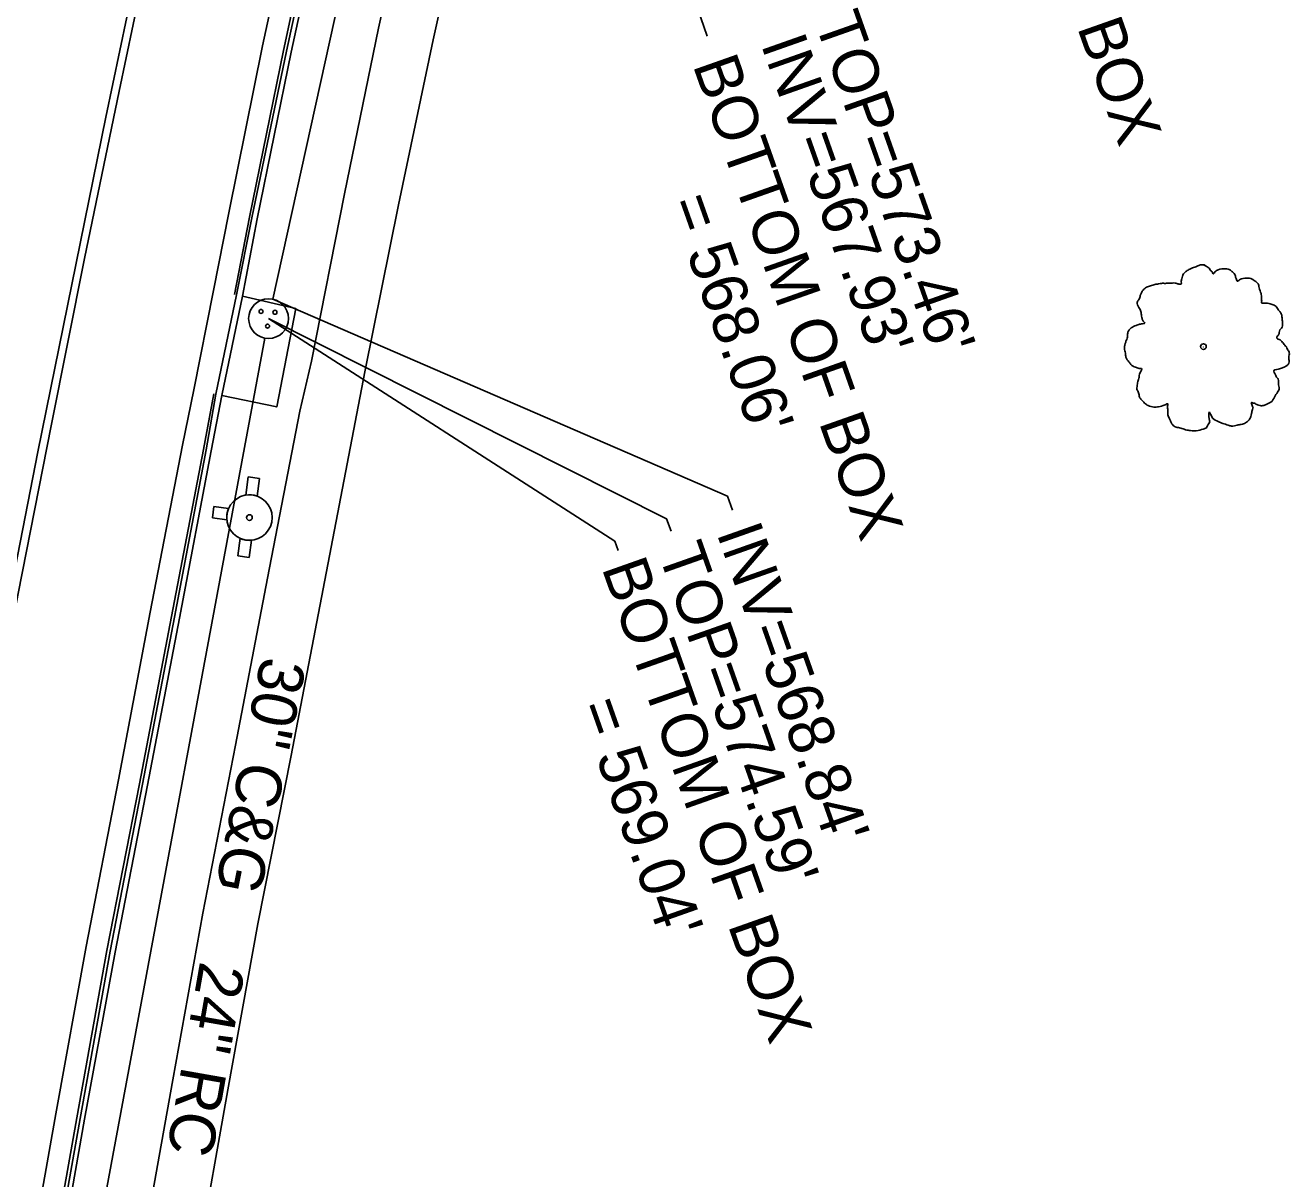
# Model space of a CAD drawing. Extents: x 2004847 to 2009016, y 1134161 to 1140101.
# Drawn here: x 2007604.1 to 2007715.2, y 1138175.3 to 1138276.6 of the extents above; entities that cross this region are included whole.
import ezdxf

# ---------------------------------------------------------------- set-up
doc = ezdxf.new("R2010")
doc.units = 0
for name, color, linetype in [('RD_EX_Conc', 7, 'Continuous'), ('RD_EX_Curb', 7, 'Continuous'), ('RD_EX_DR_Inlet', 7, 'Continuous'), ('RD_EX_DR_Inlet_txCode', 7, 'Continuous'), ('RD_EX_DR_Pipe', 7, 'Continuous'), ('RD_EX_DR_Pipe_txCode', 7, 'Continuous'), ('RD_EX_Pavement_Markings', 7, 'Continuous'), ('RD_EX_Road', 7, 'Continuous'), ('RD_EX_UT', 7, 'Continuous'), ('RD_EX_VEG', 7, 'Continuous'), ('RD_Sketch3', 7, 'Continuous')]:
    doc.layers.add(name, color=color, linetype=linetype)

msp = doc.modelspace()

# ---------------------------------------------------------------- linework, layer by layer
at = {"layer": 'RD_EX_Conc'}
for points in [[(2007649.16, 1138356.62), (2007652.36, 1138353.9), (2007650.26, 1138344.19), (2007648.01, 1138334.9), (2007644.81, 1138320.22), (2007641.56, 1138305.63), (2007638.36, 1138290.97), (2007635.14, 1138276.36), (2007632.14, 1138261.8), (2007629.25, 1138247.1), (2007628.22, 1138242.7)], [(2007652.89, 1138333.81), (2007649.68, 1138319.12), (2007646.44, 1138304.56), (2007643.17, 1138289.9), (2007639.95, 1138275.32), (2007636.89, 1138260.84), (2007633.94, 1138246.17), (2007633.09, 1138241.72)], [(2007628.22, 1138242.7), (2007625.4, 1138228.04), (2007622.58, 1138213.36), (2007619.71, 1138198.59), (2007617.06, 1138183.96), (2007614.44, 1138169.22), (2007611.75, 1138154.48), (2007609.19, 1138139.62), (2007606.66, 1138124.98), (2007604.16, 1138110.19), (2007601.88, 1138095.45), (2007601.14, 1138090.35)], [(2007633.09, 1138241.72), (2007630.28, 1138227.09), (2007627.46, 1138212.44), (2007624.55, 1138197.66), (2007621.91, 1138183.08), (2007619.29, 1138168.36), (2007616.61, 1138153.63), (2007614.02, 1138138.74), (2007611.47, 1138124.17), (2007608.98, 1138109.38), (2007606.7, 1138094.67), (2007605.96, 1138089.57)]]:
    msp.add_lwpolyline(points, dxfattribs=at)
at = {"layer": 'RD_EX_Curb'}
for points in [[(2007642.98, 1138345.16), (2007640.84, 1138336.5), (2007640.01, 1138332.74), (2007636.7, 1138318.16), (2007633.44, 1138303.55), (2007630.21, 1138288.94), (2007627.06, 1138274.34), (2007624.02, 1138259.7), (2007622.67, 1138252.91), (2007620.85, 1138244.2)], [(2007643.41, 1138344.99), (2007641.19, 1138336.42), (2007640.38, 1138332.66), (2007637.1, 1138318.07), (2007633.87, 1138303.46), (2007630.64, 1138288.84), (2007627.47, 1138274.25), (2007624.47, 1138259.6), (2007623.18, 1138252.81), (2007621.37, 1138244.09)], [(2007640.74, 1138336.52), (2007639.74, 1138332.8), (2007636.44, 1138318.21), (2007633.18, 1138303.61), (2007629.93, 1138289), (2007626.78, 1138274.4), (2007623.8, 1138259.74), (2007622.49, 1138252.95)], [(2007620.85, 1138244.2), (2007620, 1138239.3), (2007617.22, 1138224.6), (2007614.4, 1138209.92), (2007611.56, 1138195.25), (2007608.94, 1138180.56), (2007606.33, 1138165.85), (2007603.75, 1138151.14), (2007602.21, 1138142.85), (2007601.3, 1138138.01), (2007599.72, 1138129.32), (2007598.95, 1138123.64), (2007596.47, 1138108.88), (2007594.16, 1138094.07), (2007593.75, 1138091.54)], [(2007620.67, 1138244.23), (2007619.77, 1138239.34), (2007616.95, 1138224.66), (2007614.14, 1138209.97), (2007611.27, 1138195.31), (2007608.65, 1138180.62), (2007606.04, 1138165.9), (2007603.46, 1138151.19), (2007601.97, 1138142.89), (2007601.11, 1138138.04)], [(2007621.37, 1138244.09), (2007620.44, 1138239.21), (2007617.65, 1138224.52), (2007614.83, 1138209.83), (2007611.99, 1138195.17), (2007609.32, 1138180.49), (2007606.72, 1138165.78), (2007604.14, 1138151.07), (2007602.63, 1138142.78), (2007601.74, 1138137.93), (2007600.28, 1138129.23), (2007599.33, 1138123.58), (2007596.9, 1138108.81), (2007594.57, 1138094.01), (2007594.17, 1138091.47)]]:
    msp.add_lwpolyline(points, dxfattribs=at)
at = {"layer": 'RD_EX_DR_Inlet'}
msp.add_lwpolyline([(2007621.37, 1138244.09), (2007626.2, 1138243.08), (2007627.88, 1138251.72), (2007623.18, 1138252.81)], dxfattribs=at)
for centre, radius in [((2007625.48, 1138250.83), 1.75), ((2007624.82, 1138251.46), 0.175), ((2007626.04, 1138251.39), 0.175), ((2007625.39, 1138250.17), 0.175)]:
    msp.add_circle(centre, radius, dxfattribs=at)
at = {"layer": 'RD_EX_DR_Inlet_txCode'}
for points in [[(2007645.79, 1138343.17), (2007663.45, 1138277.25), (2007664.01, 1138275.65)], [(2007625.86, 1138252.54), (2007665.8, 1138235.22), (2007666.23, 1138233.99)], [(2007625.48, 1138250.83), (2007660.45, 1138233.25), (2007660.84, 1138232.15)], [(2007625.48, 1138250.83), (2007655.91, 1138231.27), (2007656.2, 1138230.45)]]:
    msp.add_lwpolyline(points, dxfattribs=at)
at = {"layer": 'RD_EX_DR_Pipe'}
for p, q in [((2007645.42, 1138341.46), (2007625.86, 1138252.54)), ((2007625.16, 1138249.11), (2007604.46, 1138137.83))]:
    msp.add_line(p, q, dxfattribs=at)
at = {"layer": 'RD_EX_Pavement_Markings'}
for points in [[(2007581.57, 1138106.22), (2007583.97, 1138121.03), (2007586.4, 1138135.83), (2007588.86, 1138150.63), (2007591.43, 1138165.4), (2007594.03, 1138180.18), (2007596.75, 1138194.93), (2007599.54, 1138209.67), (2007602.33, 1138224.41), (2007605.21, 1138239.13), (2007608.19, 1138253.83), (2007611.18, 1138268.53), (2007614.26, 1138283.21), (2007617.36, 1138297.88), (2007620.55, 1138312.54), (2007623.77, 1138327.19), (2007627.02, 1138341.83), (2007630.4, 1138356.45), (2007633.76, 1138371.07), (2007635.6, 1138379.12)], [(2007635.19, 1138373.48), (2007631.6, 1138358.72), (2007628.24, 1138344.1), (2007624.98, 1138329.46), (2007621.76, 1138314.81), (2007618.58, 1138300.15), (2007615.42, 1138285.49), (2007612.35, 1138270.81), (2007609.31, 1138256.12), (2007606.37, 1138241.41), (2007603.48, 1138226.69), (2007600.64, 1138211.96), (2007597.86, 1138197.22), (2007595.16, 1138182.47), (2007592.53, 1138167.7), (2007589.96, 1138152.92), (2007587.45, 1138138.13), (2007585.02, 1138123.33), (2007582.62, 1138108.52), (2007580.24, 1138093.71)]]:
    msp.add_lwpolyline(points, dxfattribs=at)
at = {"layer": 'RD_EX_Road'}
for points in [[(2007640.84, 1138345.98), (2007638.69, 1138336.98), (2007637.85, 1138333.22), (2007634.55, 1138318.63), (2007631.33, 1138304.01), (2007628.1, 1138289.39), (2007624.94, 1138274.79), (2007621.98, 1138260.12), (2007620.65, 1138253.31), (2007618.91, 1138244.58)], [(2007618.91, 1138244.58), (2007617.92, 1138239.71), (2007615.07, 1138225.03), (2007612.29, 1138210.32), (2007609.45, 1138195.65), (2007606.8, 1138180.95), (2007604.19, 1138166.23), (2007601.61, 1138151.51), (2007600.16, 1138143.19), (2007599.27, 1138138.35), (2007597.78, 1138129.64), (2007596.83, 1138123.99), (2007594.34, 1138109.22), (2007591.97, 1138094.42), (2007591.56, 1138091.89)]]:
    msp.add_lwpolyline(points, dxfattribs=at)
at = {"layer": 'RD_EX_UT'}
for p, q in [((2007623.69, 1138236.92), (2007623.48, 1138235.33)), ((2007624.68, 1138236.79), (2007623.69, 1138236.92)), ((2007624.48, 1138235.24), (2007624.68, 1138236.79)), ((2007620.68, 1138234.31), (2007620.55, 1138233.32)), ((2007621.97, 1138234.14), (2007620.68, 1138234.31)), ((2007620.55, 1138233.32), (2007621.81, 1138233.15)), ((2007622.99, 1138231.53), (2007622.79, 1138229.98)), ((2007623.78, 1138229.85), (2007623.98, 1138231.36)), ((2007622.79, 1138229.98), (2007623.78, 1138229.85))]:
    msp.add_line(p, q, dxfattribs=at)
for radius in [2, 0.25]:
    msp.add_circle((2007623.8, 1138233.35), radius, dxfattribs=at)
for start, end in [(70.2666, 99.243), (156.8272, 185.7944), (245.9204, 274.8967)]:
    msp.add_arc((2007623.8, 1138233.35), 2, start, end, dxfattribs=at)
at = {"layer": 'RD_EX_VEG'}
for centre, radius in [((2007707.61, 1138248.37), 0.25), ((2007707.6, 1138248.35), 0.0001)]:
    msp.add_circle(centre, radius, dxfattribs=at)
for points in [[(2007707.74, 1138255.53), (2007707.44, 1138255.56), (2007707.12, 1138255.46), (2007706.87, 1138255.36), (2007706.64, 1138255.28), (2007706.42, 1138255.18), (2007706.12, 1138255.01), (2007705.89, 1138254.81), (2007705.77, 1138254.56), (2007705.72, 1138254.33), (2007705.67, 1138254.06), (2007705.67, 1138253.88), (2007705.54, 1138253.86), (2007705.39, 1138253.88), (2007705.14, 1138253.96), (2007704.89, 1138253.96), (2007704.64, 1138253.96), (2007704.29, 1138253.93), (2007703.94, 1138253.93), (2007703.67, 1138253.88), (2007703.34, 1138253.84), (2007702.97, 1138253.71), (2007702.62, 1138253.59), (2007702.32, 1138253.34), (2007702.07, 1138252.86), (2007701.95, 1138252.51), (2007701.8, 1138252.26), (2007701.95, 1138251.81), (2007702.12, 1138251.46), (2007702.15, 1138251.26), (2007702.22, 1138250.84), (2007702.32, 1138250.61), (2007702.45, 1138250.41), (2007702.37, 1138250.39), (2007702, 1138250.34), (2007701.7, 1138250.24), (2007701.27, 1138250.01), (2007701.05, 1138249.79), (2007700.95, 1138249.46), (2007700.92, 1138249.11), (2007700.82, 1138248.91), (2007700.75, 1138248.64), (2007700.72, 1138248.56), (2007700.67, 1138248.24), (2007700.77, 1138247.79), (2007700.8, 1138247.44), (2007700.92, 1138247.21), (2007701.07, 1138247.04), (2007701.25, 1138246.79), (2007701.65, 1138246.56), (2007701.97, 1138246.46), (2007702.17, 1138246.44), (2007702, 1138245.94), (2007701.95, 1138245.59), (2007701.82, 1138245.19), (2007701.82, 1138245.11), (2007701.77, 1138244.64), (2007701.92, 1138244.31), (2007702, 1138243.94), (2007702.17, 1138243.71), (2007702.45, 1138243.41), (2007702.77, 1138243.19), (2007703.27, 1138243.06), (2007703.67, 1138243.09), (2007704.24, 1138243.26), (2007704.49, 1138243.34), (2007704.47, 1138243.16), (2007704.49, 1138242.79), (2007704.49, 1138242.37), (2007704.64, 1138242.04), (2007704.74, 1138241.77), (2007704.89, 1138241.52), (2007705.22, 1138241.29), (2007705.62, 1138241.22), (2007706.04, 1138241.07), (2007706.49, 1138240.99), (2007706.99, 1138240.97), (2007707.59, 1138241.12), (2007707.87, 1138241.24), (2007707.97, 1138241.42), (2007708.17, 1138241.79), (2007708.12, 1138242.02), (2007708.14, 1138242.61), (2007708.24, 1138242.44), (2007708.42, 1138242.09), (2007708.92, 1138241.79), (2007709.32, 1138241.62), (2007709.79, 1138241.47), (2007710.09, 1138241.39), (2007710.57, 1138241.47), (2007710.94, 1138241.54), (2007711.32, 1138241.67), (2007711.62, 1138241.94), (2007711.79, 1138242.22), (2007711.84, 1138242.49), (2007711.92, 1138242.86), (2007711.97, 1138243.04)], [(2007711.97, 1138243.04), (2007711.89, 1138243.21), (2007711.84, 1138243.46), (2007711.92, 1138243.44), (2007712.09, 1138243.39), (2007712.37, 1138243.26), (2007712.59, 1138243.19), (2007712.92, 1138243.21), (2007713.19, 1138243.31), (2007713.64, 1138243.59), (2007713.92, 1138244.06), (2007714.19, 1138244.46), (2007714.27, 1138244.79), (2007714.22, 1138245.01), (2007714.19, 1138245.51), (2007713.99, 1138245.76), (2007713.94, 1138245.89), (2007713.84, 1138246.29), (2007713.92, 1138246.34), (2007714.19, 1138246.39), (2007714.56, 1138246.51), (2007714.84, 1138246.64), (2007715.06, 1138246.81), (2007715.14, 1138247.04), (2007715.11, 1138247.44), (2007715.16, 1138247.84), (2007715.09, 1138247.99), (2007714.99, 1138248.14), (2007714.91, 1138248.34), (2007714.76, 1138248.49), (2007714.66, 1138248.64), (2007714.56, 1138248.74), (2007714.44, 1138248.89), (2007714.27, 1138249.01), (2007714.12, 1138249.06), (2007714.07, 1138249.21), (2007714.22, 1138249.41), (2007714.27, 1138249.51), (2007714.29, 1138249.74), (2007714.52, 1138250.09), (2007714.56, 1138250.49), (2007714.52, 1138250.91), (2007714.47, 1138251.19), (2007714.32, 1138251.46), (2007714.12, 1138251.71), (2007713.99, 1138251.89), (2007713.82, 1138252.01), (2007713.49, 1138252.14), (2007713.24, 1138252.19), (2007712.89, 1138252.19), (2007712.69, 1138252.24), (2007712.72, 1138252.29), (2007712.72, 1138252.44), (2007712.72, 1138252.71), (2007712.64, 1138253.16), (2007712.49, 1138253.66), (2007712.49, 1138253.69), (2007712.39, 1138253.93), (2007712.17, 1138254.13), (2007711.99, 1138254.23), (2007711.79, 1138254.36), (2007711.54, 1138254.38), (2007711.24, 1138254.38), (2007710.97, 1138254.33), (2007710.77, 1138254.23), (2007710.59, 1138254.11), (2007710.52, 1138254.26), (2007710.42, 1138254.56), (2007710.37, 1138254.71), (2007710.22, 1138254.88), (2007709.99, 1138255.08), (2007709.54, 1138255.21), (2007708.92, 1138255.13), (2007708.62, 1138254.93), (2007708.47, 1138254.76), (2007708.42, 1138254.88), (2007708.22, 1138255.08), (2007708.12, 1138255.26), (2007707.94, 1138255.38), (2007707.79, 1138255.48), (2007707.69, 1138255.53)]]:
    msp.add_spline(points, degree=3, dxfattribs=at)

# ---------------------------------------------------------------- texts
at = {"layer": 'RD_EX_DR_Inlet_txCode'}
for s, p in [('BOTTOM OF BOX', (2007685.41, 1138307.83)), ("TOP=573.46'", (2007673.42, 1138276.95)), ("INV=567.93'", (2007668.71, 1138274.95)), ('BOTTOM OF BOX', (2007662.72, 1138273.13)), ("= 568.06'", (2007660.64, 1138261.01)), ("INV=568.84'", (2007664.81, 1138232.02)), ("TOP=574.59'", (2007659.67, 1138230.29)), ('BOTTOM OF BOX', (2007654.72, 1138228.95)), ("= 569.04'", (2007652.67, 1138216.74))]:
    msp.add_text(s, height=4, rotation=289.4494, dxfattribs=at).set_placement(p)
at = {"layer": 'RD_EX_DR_Pipe_txCode'}
msp.add_text('24" RC', height=4, rotation=260.0412, dxfattribs=at).set_placement((2007619.48, 1138194.45))
at = {"layer": 'RD_Sketch3'}
msp.add_text('30" C&G', height=4, rotation=258.6984, dxfattribs=at).set_placement((2007624.88, 1138221.26))

doc.saveas('drawing.dxf')
